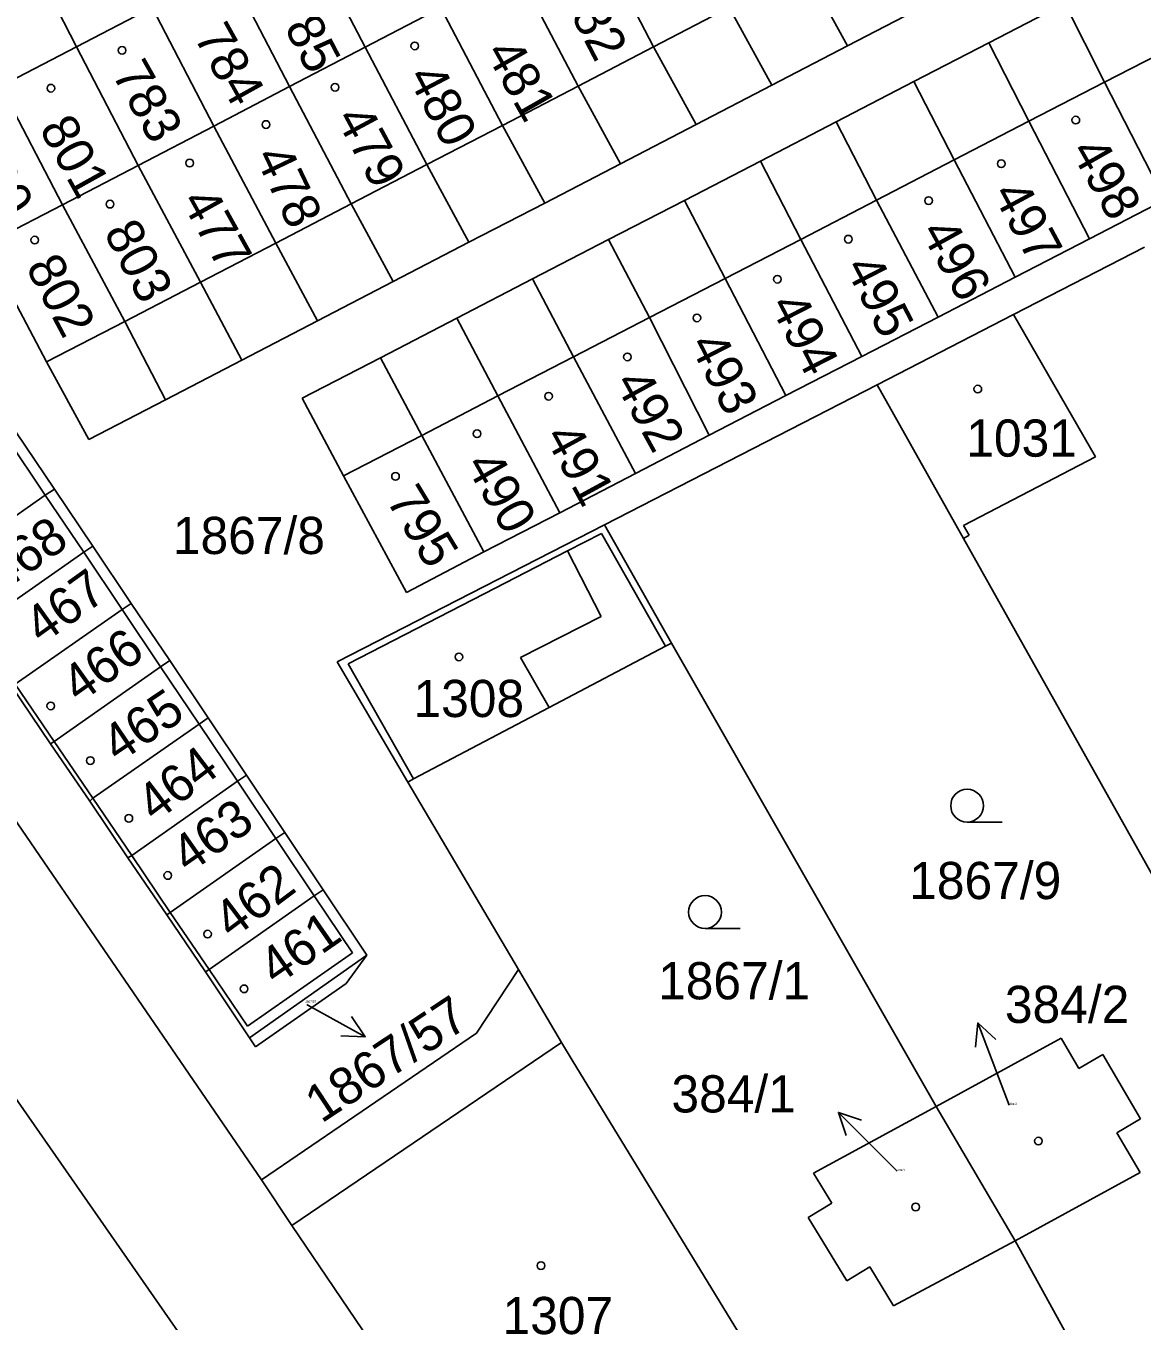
# Model space of a CAD drawing. Extents: x -763205 to -760228, y -1155311 to -1152844.
# Drawn here: x -761839.3 to -761788.3, y -1154690.1 to -1154630.9 of the extents above; entities that cross this region are included whole.
import ezdxf

# ---------------------------------------------------------------- set-up
doc = ezdxf.new("R2010")
doc.units = 0
for name, color, linetype in [('Vrstva 1', 7, 'Continuous'), ('Vrstva 16', 7, 'Continuous'), ('Vrstva 18', 7, 'Continuous'), ('Vrstva 19', 7, 'Continuous'), ('Vrstva 25', 7, 'Continuous'), ('Vrstva 4', 7, 'Continuous')]:
    doc.layers.add(name, color=color, linetype=linetype)

msp = doc.modelspace()

# ---------------------------------------------------------------- linework, layer by layer
at = {"layer": 'Vrstva 1'}
for p, q in [((-761867.91, -1154626.12), (-761828.53, -1154683.64)), ((-761826.6, -1154626.46), (-761823.78, -1154631.88)), ((-761813.41, -1154626.48), (-761810.6, -1154631.86)), ((-761838.8, -1154628.3), (-761836.98, -1154631.86)), ((-761830.06, -1154628.26), (-761827.24, -1154633.68)), ((-761816.87, -1154628.28), (-761814.05, -1154633.66)), ((-761803.69, -1154628.28), (-761801.73, -1154631.82)), ((-761795.27, -1154631.67), (-761791.8, -1154629.88)), ((-761791.8, -1154629.88), (-761789.99, -1154633.48)), ((-761833.52, -1154630.06), (-761830.7, -1154635.48)), ((-761823.78, -1154631.88), (-761820.33, -1154630.08)), ((-761820.33, -1154630.08), (-761817.51, -1154635.45)), ((-761807.15, -1154630.07), (-761805.19, -1154633.61)), ((-761801.73, -1154631.82), (-761798.26, -1154630.02)), ((-761798.7, -1154633.44), (-761795.27, -1154631.67)), ((-761795.27, -1154631.67), (-761793.45, -1154635.26)), ((-761836.98, -1154631.86), (-761834.16, -1154637.28)), ((-761827.24, -1154633.68), (-761823.78, -1154631.88)), ((-761823.78, -1154631.88), (-761820.96, -1154637.24)), ((-761810.6, -1154631.86), (-761808.65, -1154635.41)), ((-761805.19, -1154633.61), (-761801.73, -1154631.82)), ((-761802.25, -1154635.28), (-761798.7, -1154633.44)), ((-761798.7, -1154633.44), (-761796.86, -1154637.03)), ((-761840.44, -1154633.66), (-761837.62, -1154639.08)), ((-761830.7, -1154635.48), (-761827.24, -1154633.68)), ((-761827.24, -1154633.68), (-761824.42, -1154639.04)), ((-761814.05, -1154633.66), (-761812.11, -1154637.2)), ((-761808.65, -1154635.41), (-761805.19, -1154633.61)), ((-761789.99, -1154633.48), (-761787.23, -1154638.85)), ((-761834.16, -1154637.28), (-761830.7, -1154635.48)), ((-761830.7, -1154635.48), (-761827.87, -1154640.83)), ((-761817.51, -1154635.45), (-761815.58, -1154639)), ((-761812.11, -1154637.2), (-761808.65, -1154635.41)), ((-761805.72, -1154637.08), (-761802.25, -1154635.28)), ((-761802.25, -1154635.28), (-761800.41, -1154638.87)), ((-761793.45, -1154635.26), (-761790.68, -1154640.63)), ((-761837.62, -1154639.08), (-761834.16, -1154637.28)), ((-761834.16, -1154637.28), (-761831.32, -1154642.62)), ((-761820.96, -1154637.24), (-761819.04, -1154640.79)), ((-761815.58, -1154639), (-761812.11, -1154637.2)), ((-761809.19, -1154638.88), (-761805.72, -1154637.08)), ((-761805.72, -1154637.08), (-761803.87, -1154640.66)), ((-761796.86, -1154637.03), (-761794.07, -1154642.38)), ((-761841.17, -1154640.92), (-761837.62, -1154639.08)), ((-761837.62, -1154639.08), (-761834.78, -1154644.42)), ((-761824.42, -1154639.04), (-761822.5, -1154642.59)), ((-761819.04, -1154640.79), (-761815.58, -1154639)), ((-761812.66, -1154640.67), (-761809.19, -1154638.88)), ((-761809.19, -1154638.88), (-761807.33, -1154642.44)), ((-761800.41, -1154638.87), (-761797.6, -1154644.21)), ((-761790.68, -1154640.63), (-761787.23, -1154638.85)), ((-761841.17, -1154640.92), (-761838.36, -1154646.26)), ((-761827.87, -1154640.83), (-761825.97, -1154644.38)), ((-761822.5, -1154642.59), (-761819.04, -1154640.79)), ((-761816.13, -1154642.47), (-761812.66, -1154640.67)), ((-761812.66, -1154640.67), (-761810.79, -1154644.23)), ((-761803.87, -1154640.66), (-761801.08, -1154646.01)), ((-761794.15, -1154644.1), (-761788.16, -1154641.02)), ((-761794.07, -1154642.38), (-761790.68, -1154640.63)), ((-761831.32, -1154642.62), (-761829.43, -1154646.18)), ((-761825.97, -1154644.38), (-761822.5, -1154642.59)), ((-761819.6, -1154644.26), (-761816.13, -1154642.47)), ((-761816.13, -1154642.47), (-761814.26, -1154646.02)), ((-761807.33, -1154642.44), (-761804.55, -1154647.8)), ((-761797.6, -1154644.21), (-761794.07, -1154642.38)), ((-761800.38, -1154647.3), (-761794.15, -1154644.1)), ((-761794.15, -1154644.1), (-761790.4, -1154650.6)), ((-761834.78, -1154644.42), (-761832.91, -1154647.99)), ((-761829.43, -1154646.18), (-761825.97, -1154644.38)), ((-761823.09, -1154646.07), (-761819.6, -1154644.26)), ((-761819.6, -1154644.26), (-761817.72, -1154647.81)), ((-761810.79, -1154644.23), (-761808.06, -1154649.61)), ((-761801.08, -1154646.01), (-761797.6, -1154644.21)), ((-761863.76, -1154645.49), (-761820.39, -1154707.72)), ((-761838.36, -1154646.26), (-761836.42, -1154649.81)), ((-761832.91, -1154647.99), (-761829.43, -1154646.18)), ((-761826.66, -1154647.92), (-761823.09, -1154646.07)), ((-761823.09, -1154646.07), (-761821.2, -1154649.62)), ((-761814.26, -1154646.02), (-761811.43, -1154651.36)), ((-761804.55, -1154647.8), (-761801.08, -1154646.01)), ((-761812.85, -1154653.7), (-761800.38, -1154647.3)), ((-761800.38, -1154647.3), (-761796.44, -1154654.33)), ((-761836.42, -1154649.81), (-761832.91, -1154647.99)), ((-761826.66, -1154647.92), (-761824.77, -1154651.46)), ((-761817.72, -1154647.81), (-761814.89, -1154653.15)), ((-761808.06, -1154649.61), (-761804.55, -1154647.8)), ((-761839.75, -1154649.45), (-761837.99, -1154652.07)), ((-761821.2, -1154649.62), (-761818.36, -1154654.94)), ((-761811.43, -1154651.36), (-761808.06, -1154649.61)), ((-761796.43, -1154653.73), (-761790.4, -1154650.6)), ((-761824.77, -1154651.46), (-761821.9, -1154656.79)), ((-761814.89, -1154653.15), (-761811.43, -1154651.36)), ((-761843.32, -1154655.78), (-761838.41, -1154652.35)), ((-761838.41, -1154652.35), (-761837.99, -1154652.07)), ((-761837.99, -1154652.07), (-761836.24, -1154654.68)), ((-761818.36, -1154654.94), (-761814.89, -1154653.15)), ((-761825.06, -1154659.97), (-761812.85, -1154653.7)), ((-761812.85, -1154653.7), (-761809.79, -1154659.11)), ((-761796.43, -1154653.73), (-761796.17, -1154654.18)), ((-761836.65, -1154654.96), (-761836.24, -1154654.68)), ((-761836.24, -1154654.68), (-761834.48, -1154657.3)), ((-761796.44, -1154654.33), (-761796.17, -1154654.18)), ((-761796.44, -1154654.33), (-761778.68, -1154685.98)), ((-761841.54, -1154658.38), (-761836.65, -1154654.96)), ((-761821.9, -1154656.79), (-761818.36, -1154654.94)), ((-761839.78, -1154660.99), (-761834.9, -1154657.58)), ((-761834.9, -1154657.58), (-761834.48, -1154657.3)), ((-761834.48, -1154657.3), (-761832.72, -1154659.91)), ((-761815.38, -1154662.06), (-761810.05, -1154659.25)), ((-761810.05, -1154659.25), (-761809.79, -1154659.11)), ((-761809.79, -1154659.11), (-761797.69, -1154680.29)), ((-761833.14, -1154660.19), (-761832.72, -1154659.91)), ((-761832.72, -1154659.91), (-761830.97, -1154662.53)), ((-761825.06, -1154659.97), (-761821.83, -1154665.46)), ((-761838, -1154663.6), (-761833.14, -1154660.19)), ((-761839.94, -1154661.1), (-761838.17, -1154663.71)), ((-761821.57, -1154665.32), (-761815.38, -1154662.06)), ((-761836.24, -1154666.2), (-761831.38, -1154662.81)), ((-761831.38, -1154662.81), (-761830.97, -1154662.53)), ((-761830.97, -1154662.53), (-761829.21, -1154665.15)), ((-761838.17, -1154663.71), (-761838, -1154663.6)), ((-761838.17, -1154663.71), (-761836.38, -1154666.34)), ((-761829.63, -1154665.42), (-761829.21, -1154665.15)), ((-761829.21, -1154665.15), (-761827.46, -1154667.76)), ((-761821.83, -1154665.46), (-761821.57, -1154665.32)), ((-761834.46, -1154668.81), (-761829.63, -1154665.42)), ((-761821.83, -1154665.46), (-761816.77, -1154674.03)), ((-761836.38, -1154666.34), (-761836.24, -1154666.2)), ((-761836.38, -1154666.34), (-761834.63, -1154668.92)), ((-761827.87, -1154668.04), (-761827.46, -1154667.76)), ((-761827.46, -1154667.76), (-761825.7, -1154670.38)), ((-761832.7, -1154671.42), (-761827.87, -1154668.04)), ((-761834.63, -1154668.92), (-761834.46, -1154668.81)), ((-761834.63, -1154668.92), (-761832.86, -1154671.53)), ((-761830.92, -1154674.02), (-761826.12, -1154670.66)), ((-761826.12, -1154670.66), (-761825.7, -1154670.38)), ((-761825.7, -1154670.38), (-761823.71, -1154673.37)), ((-761832.86, -1154671.53), (-761832.7, -1154671.42)), ((-761832.86, -1154671.53), (-761831.09, -1154674.13)), ((-761829.08, -1154677.15), (-761823.71, -1154673.37)), ((-761824.66, -1154674.66), (-761823.71, -1154673.37)), ((-761831.09, -1154674.13), (-761830.92, -1154674.02)), ((-761831.09, -1154674.13), (-761829.08, -1154677.15)), ((-761818.69, -1154676.93), (-761816.77, -1154674.03)), ((-761816.77, -1154674.03), (-761814.81, -1154677.36)), ((-761828.8, -1154677.56), (-761824.66, -1154674.66)), ((-761829.08, -1154677.15), (-761828.8, -1154677.56)), ((-761828.53, -1154683.64), (-761818.69, -1154676.93)), ((-761797.69, -1154680.29), (-761791.97, -1154677.17)), ((-761791.97, -1154677.17), (-761791.16, -1154678.55)), ((-761814.81, -1154677.36), (-761814.33, -1154678.17)), ((-761814.33, -1154678.17), (-761805.47, -1154692.64)), ((-761791.16, -1154678.55), (-761790.07, -1154677.91)), ((-761790.07, -1154677.91), (-761788.34, -1154680.85)), ((-761803.29, -1154683.34), (-761797.69, -1154680.29)), ((-761797.69, -1154680.29), (-761794.07, -1154686.43)), ((-761789.42, -1154681.49), (-761788.34, -1154680.85)), ((-761789.42, -1154681.49), (-761788.36, -1154683.3)), ((-761828.53, -1154683.64), (-761827.14, -1154685.73)), ((-761803.29, -1154683.34), (-761802.46, -1154684.71)), ((-761794.07, -1154686.43), (-761788.36, -1154683.3)), ((-761803.53, -1154685.36), (-761802.46, -1154684.71)), ((-761803.53, -1154685.36), (-761801.77, -1154688.26)), ((-761827.14, -1154685.73), (-761817.86, -1154699.39)), ((-761799.63, -1154689.39), (-761794.07, -1154686.43)), ((-761794.07, -1154686.43), (-761790.7, -1154692.54)), ((-761801.77, -1154688.26), (-761800.71, -1154687.61)), ((-761800.71, -1154687.61), (-761799.63, -1154689.39))]:
    msp.add_line(p, q, dxfattribs=at)
at = {"layer": 'Vrstva 16'}
for p, q in [((-761826.46, -1154675.62), (-761826.41, -1154675.65)), ((-761823.784, -1154677.1), (-761826.41, -1154675.65)), ((-761795.778, -1154676.467), (-761794.71, -1154679.27)), ((-761794.35, -1154680.22), (-761794.71, -1154679.27)), ((-761802.15, -1154680.558), (-761800.03, -1154682.68)), ((-761799.47, -1154683.24), (-761800.03, -1154682.68))]:
    msp.add_line(p, q, dxfattribs=at)
for points in [[(-761824.417, -1154676.179), (-761823.784, -1154677.1), (-761824.901, -1154677.054)], [(-761795.889, -1154677.579), (-761795.778, -1154676.467), (-761794.955, -1154677.223)], [(-761801.797, -1154681.619), (-761802.15, -1154680.558), (-761801.09, -1154680.912)]]:
    msp.add_lwpolyline(points, dxfattribs=at)
at = {"layer": 'Vrstva 25'}
for p, q in [((-761796.27, -1154667.29), (-761794.67, -1154667.29)), ((-761808.25, -1154672.15), (-761806.65, -1154672.15))]:
    msp.add_line(p, q, dxfattribs=at)
for centre, radius in [((-761821.52, -1154631.82), 0.175), ((-761834.9, -1154632.02), 0.175), ((-761838.15, -1154633.75), 0.175), ((-761825.16, -1154633.71), 0.175), ((-761791.3, -1154635.21), 0.175), ((-761828.32, -1154635.41), 0.175), ((-761831.81, -1154637.17), 0.175), ((-761794.71, -1154637.2), 0.175), ((-761798.03, -1154638.89), 0.175), ((-761835.45, -1154639.05), 0.175), ((-761838.89, -1154640.69), 0.175), ((-761801.7, -1154640.65), 0.175), ((-761804.94, -1154642.48), 0.175), ((-761808.62, -1154644.25), 0.175), ((-761811.8, -1154646.03), 0.175), ((-761815.4, -1154647.83), 0.175), ((-761795.78, -1154647.5), 0.175), ((-761818.67, -1154649.54), 0.175), ((-761822.4, -1154651.49), 0.175), ((-761819.5, -1154659.74), 0.175), ((-761838.16, -1154661.98), 0.175), ((-761836.35, -1154664.48), 0.175), ((-761796.27, -1154666.54), 0.75), ((-761834.59, -1154667.12), 0.175), ((-761832.81, -1154669.73), 0.175), ((-761808.25, -1154671.4), 0.75), ((-761830.99, -1154672.41), 0.175), ((-761829.32, -1154674.91), 0.175), ((-761793.01, -1154681.87), 0.175), ((-761798.62, -1154684.88), 0.175), ((-761815.75, -1154687.56), 0.175)]:
    msp.add_circle(centre, radius, dxfattribs=at)
at = {"layer": 'Vrstva 4'}
for p, q in [((-761836.98, -1154631.86), (-761833.52, -1154630.06)), ((-761810.6, -1154631.86), (-761807.15, -1154630.07)), ((-761789.99, -1154633.48), (-761786.39, -1154631.62)), ((-761840.44, -1154633.66), (-761836.98, -1154631.86)), ((-761814.05, -1154633.66), (-761810.6, -1154631.86)), ((-761817.51, -1154635.45), (-761814.05, -1154633.66)), ((-761793.45, -1154635.26), (-761789.99, -1154633.48)), ((-761820.96, -1154637.24), (-761817.51, -1154635.45)), ((-761796.86, -1154637.03), (-761793.45, -1154635.26)), ((-761824.42, -1154639.04), (-761820.96, -1154637.24)), ((-761800.41, -1154638.87), (-761796.86, -1154637.03)), ((-761827.87, -1154640.83), (-761824.42, -1154639.04)), ((-761803.87, -1154640.66), (-761800.41, -1154638.87)), ((-761831.32, -1154642.62), (-761827.87, -1154640.83)), ((-761807.33, -1154642.44), (-761803.87, -1154640.66)), ((-761834.78, -1154644.42), (-761831.32, -1154642.62)), ((-761810.79, -1154644.23), (-761807.33, -1154642.44)), ((-761838.36, -1154646.26), (-761834.78, -1154644.42)), ((-761814.26, -1154646.02), (-761810.79, -1154644.23)), ((-761817.72, -1154647.81), (-761814.26, -1154646.02)), ((-761821.2, -1154649.62), (-761817.72, -1154647.81)), ((-761840.16, -1154649.73), (-761838.41, -1154652.35)), ((-761824.77, -1154651.46), (-761821.2, -1154649.62)), ((-761838.41, -1154652.35), (-761836.65, -1154654.96)), ((-761814.54, -1154654.9), (-761812.98, -1154654.1)), ((-761812.98, -1154654.1), (-761810.05, -1154659.25)), ((-761836.65, -1154654.96), (-761834.9, -1154657.58)), ((-761818.34, -1154656.86), (-761814.54, -1154654.9)), ((-761814.54, -1154654.9), (-761813, -1154657.9)), ((-761824.57, -1154660.05), (-761818.34, -1154656.86)), ((-761834.9, -1154657.58), (-761833.14, -1154660.19)), ((-761816.68, -1154659.77), (-761813, -1154657.9)), ((-761824.57, -1154660.05), (-761821.57, -1154665.32)), ((-761816.68, -1154659.77), (-761815.38, -1154662.06)), ((-761833.14, -1154660.19), (-761831.38, -1154662.81)), ((-761839.78, -1154660.99), (-761838, -1154663.6)), ((-761831.38, -1154662.81), (-761829.63, -1154665.42)), ((-761838, -1154663.6), (-761836.24, -1154666.2)), ((-761829.63, -1154665.42), (-761827.87, -1154668.04)), ((-761836.24, -1154666.2), (-761834.46, -1154668.81)), ((-761827.87, -1154668.04), (-761826.12, -1154670.66)), ((-761834.46, -1154668.81), (-761832.7, -1154671.42)), ((-761826.12, -1154670.66), (-761824.36, -1154673.27)), ((-761832.7, -1154671.42), (-761830.92, -1154674.02)), ((-761829.16, -1154676.62), (-761824.36, -1154673.27)), ((-761830.92, -1154674.02), (-761829.16, -1154676.62)), ((-761827.14, -1154685.73), (-761814.81, -1154677.36))]:
    msp.add_line(p, q, dxfattribs=at)

# ---------------------------------------------------------------- texts
at = {"layer": 'Vrstva 16'}
for s, p in [('384/2', (-761794.543, -1154676.47)), ('384/1', (-761809.786, -1154680.56))]:
    msp.add_text(s, height=1.7, dxfattribs=at).set_placement(p)
msp.add_text('1867/57', height=1.7, rotation=33.46074, dxfattribs=at).set_placement((-761825.785, -1154681.082))
at = {"layer": 'Vrstva 18'}
for s, height, p in [('1867/8', 1.7, (-761832.577, -1154655.04)), ('1867/9', 1.7, (-761798.917, -1154670.81)), ('1867/1', 1.7, (-761810.397, -1154675.39)), ('1867/57', 0.1, (-761826.527, -1154675.54))]:
    msp.add_text(s, height=height, dxfattribs=at).set_placement(p)
at = {"layer": 'Vrstva 19'}
for s, rotation, p in [('785', 297.47969, (-761828.09, -1154629.841)), ('482', 297.53698, (-761814.99, -1154629.271)), ('784', 299.14126, (-761831.644, -1154631.387)), ('481', 299.65693, (-761818.323, -1154632.116)), ('783', 299.48504, (-761835.393, -1154633.087)), ('480', 297.70887, (-761821.87, -1154633.22)), ('801', 299.08397, (-761838.715, -1154635.597)), ('479', 298.22453, (-761825.158, -1154635.119)), ('800', 299.02667, (-761842.185, -1154636.498)), ('498', 299.54234, (-761791.573, -1154636.617)), ('478', 295.47434, (-761828.848, -1154636.864)), ('477', 299.08397, (-761832.225, -1154638.907)), ('497', 298.28183, (-761795.138, -1154638.559)), ('803', 297.42239, (-761835.761, -1154640.331)), ('496', 299.02667, (-761798.425, -1154640.308)), ('802', 297.93805, (-761839.329, -1154641.92)), ('495', 297.19321, (-761801.882, -1154641.921)), ('494', 297.07862, (-761805.312, -1154643.651)), ('493', 297.2505, (-761808.991, -1154645.451)), ('492', 298.85479, (-761812.415, -1154647.198)), ('491', 298.56831, (-761815.616, -1154649.659)), ('490', 299.59963, (-761819.233, -1154650.956)), ('795', 301.26121, (-761822.857, -1154652.563)), ('468', 34.77854, (-761840.365, -1154656.785)), ('467', 35.63798, (-761838.567, -1154659.212)), ('466', 35.46609, (-761836.867, -1154661.902)), ('465', 34.03369, (-761835.073, -1154664.627)), ('464', 37.29955, (-761833.391, -1154667.346)), ('463', 35.00772, (-761831.866, -1154669.684)), ('462', 36.89848, (-761829.88, -1154672.687)), ('461', 34.83583, (-761827.865, -1154674.814))]:
    msp.add_text(s, height=1.7, rotation=rotation, dxfattribs=at).set_placement(p)
for s, height, p in [('1031', 1.7, (-761796.307, -1154650.59)), ('1308', 1.7, (-761821.577, -1154662.49)), ('384/2', 0.1, (-761794.336, -1154680.22)), ('384/1', 0.1, (-761799.456, -1154683.24)), ('1307', 1.7, (-761817.507, -1154690.69))]:
    msp.add_text(s, height=height, dxfattribs=at).set_placement(p)

doc.saveas('drawing.dxf')
